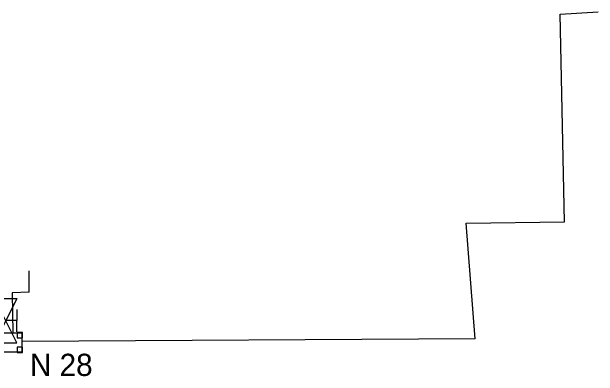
# Model space of a CAD drawing. Extents: x -642943 to -623314, y -1138561 to -1113539.
# Drawn here: x -641582 to -641502.6, y -1115431.7 to -1115382.4 of the extents above; entities that cross this region are included whole.
import ezdxf

# ---------------------------------------------------------------- set-up
doc = ezdxf.new("R2010")
doc.units = 0
for name, color, linetype in [('horkovod armatury', 7, 'Continuous'), ('horkovod předisol', 7, 'Continuous'), ('horkovod trasa', 7, 'Continuous'), ('horkovod číslo šachty', 7, 'Continuous'), ('horkovod šachty', 7, 'Continuous')]:
    doc.layers.add(name, color=color, linetype=linetype)

# ---------------------------------------------------------------- blocks, each defined once
blk = doc.blocks.new('POINT_DISPLAY')
blk.add_line((0, 0), (0, 0))
blk = doc.blocks.new('SCH_01_5')
at = {"layer": 'horkovod armatury'}
for p, q in [((10, 5), (-10, -5)), ((-10, -5), (-10, 5)), ((-10, 5), (10, -5)), ((-5, 5), (0, 5)), ((0, 5), (0, 0)), ((5, 5), (0, 5)), ((10, -5), (10, 5))]:
    blk.add_line(p, q, dxfattribs=at)

msp = doc.modelspace()

# ---------------------------------------------------------------- linework, layer by layer
at = {"layer": 'horkovod předisol'}
for p, q in [((-641507.78, -1115382.704), (-641502.632, -1115382.38)), ((-641507.184, -1115410.76), (-641507.78, -1115382.704)), ((-641520.508, -1115410.938), (-641507.184, -1115410.76)), ((-641519.278, -1115426.579), (-641520.508, -1115410.938)), ((-641519.278, -1115426.579), (-641580.558, -1115426.958))]:
    msp.add_line(p, q, dxfattribs=at)
at = {"layer": 'horkovod trasa'}
for p, q in [((-641507.78, -1115382.704), (-641502.632, -1115382.38)), ((-641507.184, -1115410.76), (-641507.78, -1115382.704)), ((-641520.508, -1115410.938), (-641507.184, -1115410.76)), ((-641519.278, -1115426.579), (-641520.508, -1115410.938)), ((-641579.575, -1115420.271), (-641579.615, -1115417.421)), ((-641579.575, -1115420.271), (-641581.883, -1115420.37)), ((-641581.883, -1115420.37), (-641581.808, -1115425.822)), ((-641519.278, -1115426.579), (-641580.558, -1115426.958))]:
    msp.add_line(p, q, dxfattribs=at)
at = {"layer": 'horkovod šachty'}
for p, q in [((-641581.219, -1115425.75), (-641581.219, -1115426.45)), ((-641580.519, -1115425.75), (-641581.219, -1115425.75)), ((-641580.519, -1115426.45), (-641580.519, -1115425.75)), ((-641581.219, -1115426.45), (-641580.519, -1115426.45)), ((-641581.219, -1115427.72), (-641581.219, -1115428.42)), ((-641580.519, -1115427.72), (-641581.219, -1115427.72)), ((-641580.519, -1115428.42), (-641580.519, -1115427.72)), ((-641581.219, -1115428.42), (-641580.519, -1115428.42))]:
    msp.add_line(p, q, dxfattribs=at)
msp.add_lwpolyline([(-641580.558, -1115428.358), (-641580.558, -1115425.818), (-641583.128, -1115425.826), (-641583.128, -1115428.359), (-641580.558, -1115428.358)], dxfattribs=at)

# ---------------------------------------------------------------- block references
at = {"layer": 'horkovod armatury', "xscale": 0.29998068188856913, "yscale": 0.2999806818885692, "rotation": -89.83990665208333}
msp.add_blockref('SCH_01_5', (-641582.771, -1115424.139), dxfattribs=at)
at = {"layer": 'horkovod šachty'}
for p in [(-641580.869, -1115426.1), (-641580.869, -1115428.07)]:
    msp.add_blockref('POINT_DISPLAY', p, dxfattribs=at)

# ---------------------------------------------------------------- texts
at = {"layer": 'horkovod číslo šachty'}
msp.add_text('N 28', height=3, dxfattribs=at).set_placement((-641579.493, -1115431.612))

doc.saveas('drawing.dxf')
